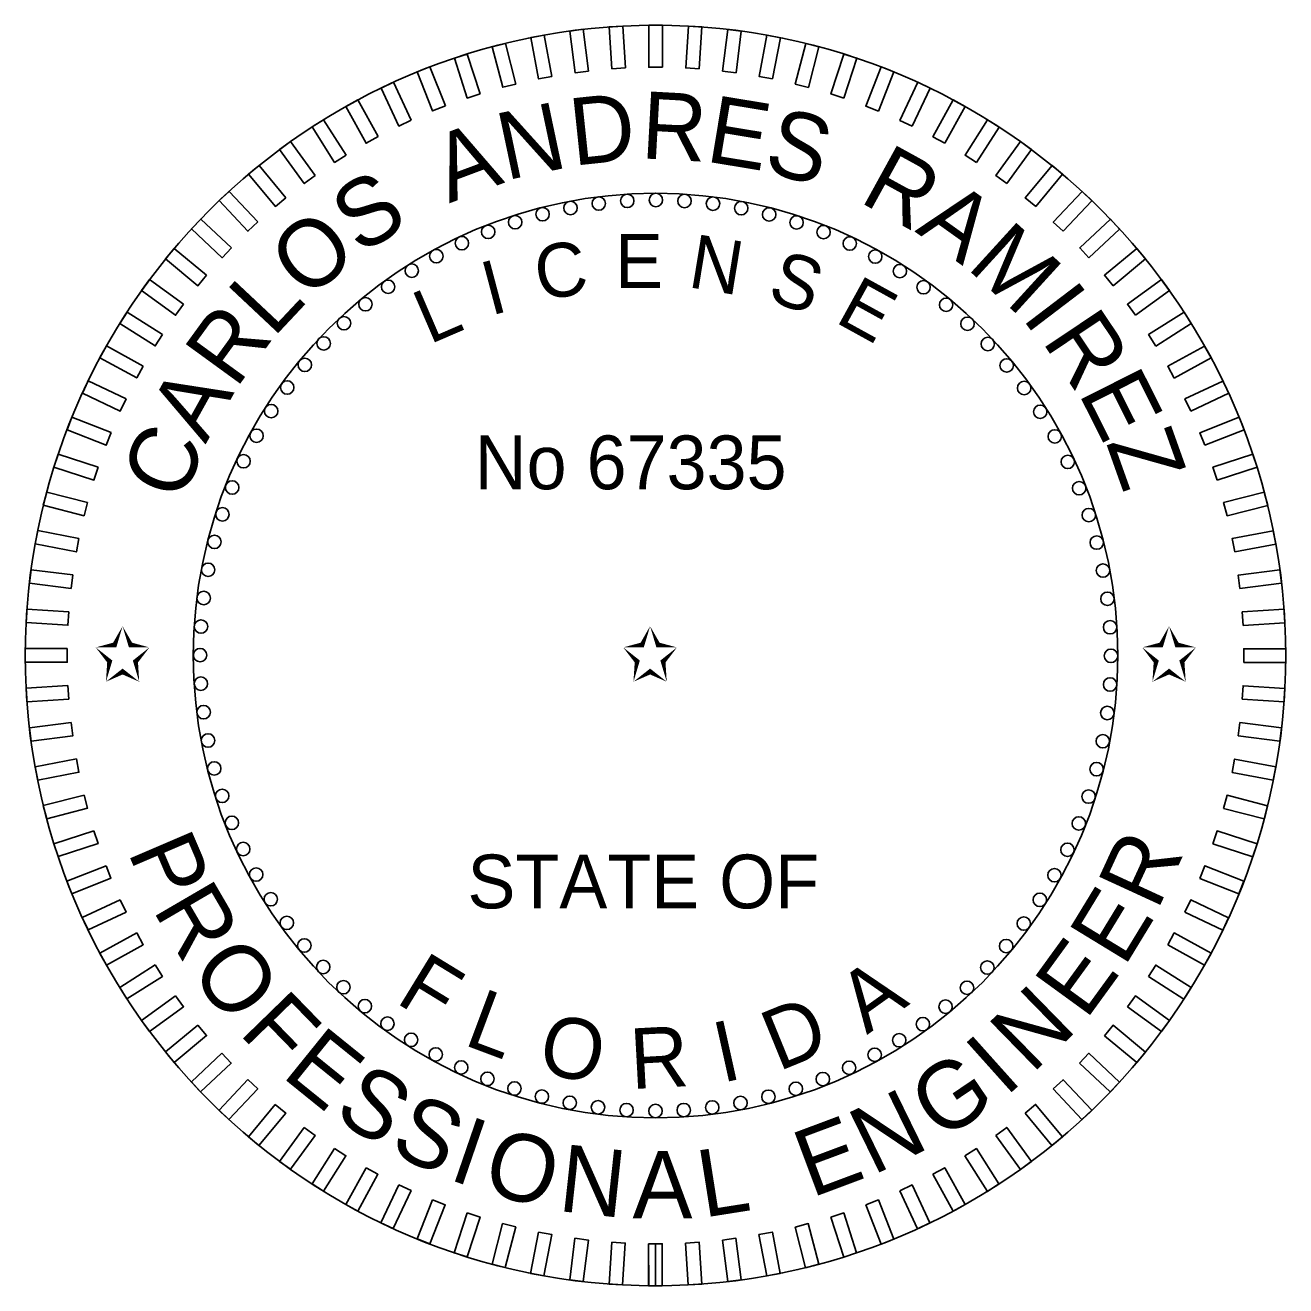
# Model space of a CAD drawing. Extents: x -0.86 to 1.33, y -1.26 to 1.83.
# Drawn here: x 0.0936 to 0.2497, y 1.6752 to 1.8314 of the extents above; entities that cross this region are included whole.
import ezdxf

# ---------------------------------------------------------------- set-up
doc = ezdxf.new("R2010")
doc.units = 0
for name, color, linetype in [('FLMap1', 7, 'Continuous'), ('FLMap3', 7, 'Continuous'), ('TextMisc', 7, 'Continuous')]:
    doc.layers.add(name, color=color, linetype=linetype)

msp = doc.modelspace()

# ---------------------------------------------------------------- linework, layer by layer
at = {"layer": 'FLMap1'}
for radius in [0.07809, 0.05727]:
    msp.add_circle((0.17165, 1.75334), radius, dxfattribs=at)
at = {"layer": 'FLMap3'}
for p, q in [((0.17082, 1.67525), (0.1708, 1.68045)), ((0.17165, 1.67525), (0.17163, 1.68046)), ((0.17248, 1.67525), (0.17247, 1.68046))]:
    msp.add_line(p, q, dxfattribs=at)
for points in [[(0.16336, 1.82576), (0.16169, 1.82555), (0.16104, 1.83071), (0.1627, 1.83093)], [(0.16792, 1.82614), (0.16624, 1.82604), (0.16591, 1.83123), (0.16759, 1.83133)], [(0.1725, 1.82623), (0.17082, 1.82623), (0.17082, 1.83143), (0.1725, 1.83143)], [(0.17707, 1.82604), (0.17539, 1.82614), (0.17572, 1.83133), (0.1774, 1.83123)], [(0.18163, 1.82555), (0.17996, 1.82576), (0.18061, 1.83092), (0.18228, 1.83071)], [(0.15434, 1.82415), (0.15272, 1.82374), (0.15142, 1.82877), (0.15305, 1.82919)], [(0.15882, 1.8251), (0.15717, 1.82479), (0.1562, 1.8299), (0.15785, 1.83021)], [(0.18614, 1.82478), (0.18449, 1.8251), (0.18546, 1.83021), (0.18712, 1.82989)], [(0.1906, 1.82373), (0.18897, 1.82415), (0.19026, 1.82919), (0.19189, 1.82877)], [(0.14993, 1.82293), (0.14833, 1.82241), (0.14673, 1.82736), (0.14832, 1.82787)], [(0.19498, 1.8224), (0.19338, 1.82292), (0.19499, 1.82787), (0.19659, 1.82735)], [(0.14561, 1.82143), (0.14404, 1.82081), (0.14213, 1.82564), (0.14369, 1.82626)], [(0.19927, 1.8208), (0.19771, 1.82142), (0.19962, 1.82626), (0.20119, 1.82564)], [(0.14138, 1.81966), (0.13986, 1.81894), (0.13765, 1.82365), (0.13917, 1.82436)], [(0.20345, 1.81893), (0.20193, 1.81965), (0.20415, 1.82436), (0.20567, 1.82364)], [(0.13728, 1.81763), (0.1358, 1.81682), (0.1333, 1.82137), (0.13477, 1.82218)], [(0.20751, 1.81681), (0.20603, 1.81762), (0.20854, 1.82218), (0.21001, 1.82137)], [(0.13331, 1.81534), (0.13189, 1.81444), (0.1291, 1.81883), (0.13052, 1.81973)], [(0.21142, 1.81443), (0.21, 1.81533), (0.21279, 1.81972), (0.21421, 1.81882)], [(0.12949, 1.81281), (0.12813, 1.81182), (0.12507, 1.81603), (0.12644, 1.81702)], [(0.21518, 1.81181), (0.21382, 1.8128), (0.21688, 1.81701), (0.21824, 1.81602)], [(0.12584, 1.81005), (0.12455, 1.80898), (0.12123, 1.81298), (0.12253, 1.81405)], [(0.21877, 1.80897), (0.21747, 1.81004), (0.22078, 1.81404), (0.22208, 1.81297)], [(0.12237, 1.80706), (0.12115, 1.80591), (0.11759, 1.8097), (0.11881, 1.81085)], [(0.22216, 1.8059), (0.22094, 1.80705), (0.2245, 1.81084), (0.22573, 1.80969)], [(0.1191, 1.80386), (0.11794, 1.80263), (0.11415, 1.80619), (0.1153, 1.80742)], [(0.22536, 1.80262), (0.22421, 1.80385), (0.22801, 1.80741), (0.22916, 1.80618)], [(0.11603, 1.80046), (0.11496, 1.79916), (0.11095, 1.80248), (0.11202, 1.80377)], [(0.22835, 1.79915), (0.22728, 1.80045), (0.23129, 1.80376), (0.23236, 1.80247)], [(0.11318, 1.79687), (0.11219, 1.79551), (0.10798, 1.79857), (0.10897, 1.79993)], [(0.23112, 1.7955), (0.23013, 1.79686), (0.23434, 1.79992), (0.23533, 1.79856)], [(0.11056, 1.79312), (0.10966, 1.7917), (0.10527, 1.79448), (0.10617, 1.7959)], [(0.23365, 1.79168), (0.23275, 1.7931), (0.23714, 1.79589), (0.23804, 1.79447)], [(0.10818, 1.7892), (0.10737, 1.78773), (0.10282, 1.79023), (0.10363, 1.79171)], [(0.23593, 1.78771), (0.23512, 1.78919), (0.23968, 1.79169), (0.24049, 1.79022)], [(0.10606, 1.78515), (0.10534, 1.78362), (0.10064, 1.78584), (0.10135, 1.78736)], [(0.23796, 1.78361), (0.23725, 1.78513), (0.24195, 1.78735), (0.24267, 1.78583)], [(0.10419, 1.78096), (0.10357, 1.7794), (0.09874, 1.78132), (0.09935, 1.78288)], [(0.23973, 1.77939), (0.23911, 1.78095), (0.24395, 1.78287), (0.24457, 1.7813)], [(0.10259, 1.77667), (0.10207, 1.77508), (0.09712, 1.77668), (0.09764, 1.77828)], [(0.24123, 1.77506), (0.24071, 1.77666), (0.24566, 1.77827), (0.24618, 1.77667)], [(0.10126, 1.77229), (0.10084, 1.77066), (0.0958, 1.77196), (0.09622, 1.77359)], [(0.24246, 1.77065), (0.24204, 1.77228), (0.24708, 1.77357), (0.2475, 1.77194)], [(0.10021, 1.76784), (0.09989, 1.76618), (0.09479, 1.76716), (0.0951, 1.76881)], [(0.24341, 1.76617), (0.24309, 1.76782), (0.2482, 1.76879), (0.24852, 1.76714)], [(0.09944, 1.76332), (0.09923, 1.76165), (0.09407, 1.7623), (0.09428, 1.76397)], [(0.24407, 1.76164), (0.24386, 1.76331), (0.24902, 1.76396), (0.24923, 1.76229)], [(0.09896, 1.75877), (0.09885, 1.75709), (0.09366, 1.75742), (0.09377, 1.75909)], [(0.24445, 1.75707), (0.24434, 1.75875), (0.24953, 1.75908), (0.24964, 1.7574)], [(0.09876, 1.75419), (0.09876, 1.75251), (0.09356, 1.75251), (0.09356, 1.75419)], [(0.24454, 1.75249), (0.24454, 1.75418), (0.24974, 1.75418), (0.24974, 1.75249)], [(0.09885, 1.74961), (0.09896, 1.74794), (0.09376, 1.74761), (0.09366, 1.74929)], [(0.24434, 1.74792), (0.24445, 1.7496), (0.24964, 1.74927), (0.24953, 1.74759)], [(0.09923, 1.74505), (0.09944, 1.74338), (0.09428, 1.74273), (0.09407, 1.7444)], [(0.24386, 1.74337), (0.24407, 1.74503), (0.24923, 1.74438), (0.24902, 1.74271)], [(0.09989, 1.74052), (0.10021, 1.73887), (0.0951, 1.73789), (0.09478, 1.73954)], [(0.24309, 1.73885), (0.2434, 1.7405), (0.24851, 1.73953), (0.2482, 1.73788)], [(0.10084, 1.73604), (0.10126, 1.73441), (0.09622, 1.73312), (0.0958, 1.73474)], [(0.24204, 1.73439), (0.24246, 1.73602), (0.24749, 1.73473), (0.24708, 1.7331)], [(0.10206, 1.73163), (0.10258, 1.73003), (0.09764, 1.72842), (0.09712, 1.73002)], [(0.24071, 1.73001), (0.24123, 1.73161), (0.24618, 1.73), (0.24566, 1.7284)], [(0.10357, 1.7273), (0.10418, 1.72574), (0.09935, 1.72382), (0.09873, 1.72538)], [(0.23911, 1.72572), (0.23973, 1.72729), (0.24456, 1.72537), (0.24394, 1.72381)], [(0.10534, 1.72308), (0.10605, 1.72155), (0.10135, 1.71934), (0.10063, 1.72086)], [(0.23724, 1.72154), (0.23796, 1.72306), (0.24266, 1.72085), (0.24195, 1.71933)], [(0.10737, 1.71897), (0.10818, 1.7175), (0.10362, 1.71499), (0.10281, 1.71647)], [(0.23511, 1.71748), (0.23592, 1.71896), (0.24048, 1.71645), (0.23967, 1.71498)], [(0.10965, 1.715), (0.11055, 1.71358), (0.10616, 1.7108), (0.10526, 1.71222)], [(0.23274, 1.71357), (0.23364, 1.71499), (0.23803, 1.7122), (0.23713, 1.71078)], [(0.11218, 1.71119), (0.11317, 1.70983), (0.10896, 1.70677), (0.10797, 1.70813)], [(0.23012, 1.70981), (0.23111, 1.71117), (0.23532, 1.70812), (0.23433, 1.70676)], [(0.11495, 1.70754), (0.11602, 1.70624), (0.11201, 1.70292), (0.11094, 1.70422)], [(0.22727, 1.70623), (0.22834, 1.70752), (0.23235, 1.70421), (0.23128, 1.70291)], [(0.11793, 1.70407), (0.11909, 1.70284), (0.11529, 1.69928), (0.11414, 1.7005)], [(0.2242, 1.70283), (0.22535, 1.70405), (0.22915, 1.70049), (0.22799, 1.69927)], [(0.12113, 1.70079), (0.12236, 1.69964), (0.1188, 1.69585), (0.11757, 1.697)], [(0.22093, 1.69963), (0.22215, 1.70078), (0.22571, 1.69699), (0.22449, 1.69584)], [(0.12453, 1.69772), (0.12583, 1.69665), (0.12251, 1.69264), (0.12122, 1.69371)], [(0.21746, 1.69664), (0.21875, 1.69771), (0.22207, 1.6937), (0.22077, 1.69263)], [(0.12812, 1.69487), (0.12948, 1.69388), (0.12642, 1.68968), (0.12506, 1.69066)], [(0.21381, 1.69388), (0.21517, 1.69486), (0.21822, 1.69066), (0.21686, 1.68967)], [(0.13188, 1.69225), (0.1333, 1.69135), (0.13051, 1.68696), (0.12909, 1.68786)], [(0.20999, 1.69135), (0.21141, 1.69225), (0.2142, 1.68786), (0.21278, 1.68695)], [(0.13579, 1.68988), (0.13726, 1.68907), (0.13476, 1.68451), (0.13329, 1.68532)], [(0.20602, 1.68906), (0.20749, 1.68987), (0.21, 1.68531), (0.20853, 1.6845)], [(0.13985, 1.68775), (0.14137, 1.68704), (0.13915, 1.68233), (0.13763, 1.68305)], [(0.20192, 1.68703), (0.20344, 1.68775), (0.20565, 1.68304), (0.20413, 1.68232)], [(0.14403, 1.68588), (0.14559, 1.68527), (0.14368, 1.68043), (0.14211, 1.68105)], [(0.19769, 1.68526), (0.19926, 1.68588), (0.20117, 1.68104), (0.19961, 1.68042)], [(0.14832, 1.68428), (0.14992, 1.68376), (0.14831, 1.67882), (0.14671, 1.67934)], [(0.19337, 1.68376), (0.19497, 1.68428), (0.19657, 1.67933), (0.19497, 1.67881)], [(0.1527, 1.68295), (0.15433, 1.68254), (0.15304, 1.6775), (0.15141, 1.67792)], [(0.18895, 1.68253), (0.19058, 1.68295), (0.19188, 1.67791), (0.19025, 1.67749)], [(0.15716, 1.6819), (0.15881, 1.68159), (0.15783, 1.67648), (0.15618, 1.67679)], [(0.16167, 1.68113), (0.16334, 1.68092), (0.16269, 1.67576), (0.16102, 1.67597)], [(0.16623, 1.68065), (0.1679, 1.68054), (0.16758, 1.67535), (0.1659, 1.67546)], [(0.17538, 1.68054), (0.17706, 1.68065), (0.17738, 1.67546), (0.17571, 1.67535)], [(0.17994, 1.68092), (0.18161, 1.68113), (0.18226, 1.67597), (0.1806, 1.67576)], [(0.18447, 1.68159), (0.18613, 1.6819), (0.1871, 1.67679), (0.18545, 1.67648)], [(0.1708, 1.68045), (0.17248, 1.68045), (0.17248, 1.67525), (0.1708, 1.67525)]]:
    msp.add_lwpolyline(points, close=True, dxfattribs=at)
for centre in [(0.16815, 1.80967), (0.1717, 1.80978), (0.17524, 1.80966), (0.15766, 1.80802), (0.16112, 1.80879), (0.16462, 1.80934), (0.17877, 1.80933), (0.18227, 1.80877), (0.18573, 1.80799), (0.15426, 1.80703), (0.18913, 1.807), (0.15092, 1.80583), (0.19247, 1.8058), (0.14766, 1.80443), (0.19572, 1.80439), (0.1445, 1.80282), (0.19888, 1.80277), (0.14145, 1.80102), (0.20193, 1.80097), (0.13852, 1.79903), (0.20486, 1.79897), (0.13571, 1.79686), (0.20766, 1.7968), (0.13305, 1.79451), (0.21031, 1.79445), (0.13054, 1.79201), (0.21282, 1.79194), (0.1282, 1.78935), (0.21516, 1.78928), (0.12602, 1.78655), (0.21733, 1.78648), (0.12403, 1.78362), (0.21932, 1.78354), (0.12222, 1.78057), (0.22112, 1.78049), (0.12061, 1.77741), (0.22273, 1.77733), (0.1192, 1.77416), (0.22414, 1.77407), (0.11799, 1.77083), (0.22534, 1.77074), (0.117, 1.76742), (0.22632, 1.76733), (0.11622, 1.76396), (0.22709, 1.76387), (0.11567, 1.76046), (0.22764, 1.76037), (0.11533, 1.75693), (0.22797, 1.75684), (0.11522, 1.75339), (0.22808, 1.7533), (0.11532, 1.74985), (0.22797, 1.74975), (0.11566, 1.74632), (0.22763, 1.74622), (0.11621, 1.74281), (0.22707, 1.74272), (0.11698, 1.73935), (0.2263, 1.73926), (0.11796, 1.73595), (0.22531, 1.73586), (0.11916, 1.73261), (0.2241, 1.73253), (0.12057, 1.72936), (0.22269, 1.72927), (0.12217, 1.7262), (0.22108, 1.72612), (0.12398, 1.72314), (0.21927, 1.72307), (0.12597, 1.72021), (0.21728, 1.72013), (0.12814, 1.71741), (0.2151, 1.71734), (0.13048, 1.71475), (0.21276, 1.71468), (0.13298, 1.71224), (0.21025, 1.71217), (0.13564, 1.70989), (0.20759, 1.70983), (0.13844, 1.70772), (0.20478, 1.70766), (0.14137, 1.70572), (0.20185, 1.70567), (0.14442, 1.70391), (0.1988, 1.70387), (0.14758, 1.7023), (0.19564, 1.70226), (0.15083, 1.70089), (0.19238, 1.70086), (0.15417, 1.69969), (0.15757, 1.69869), (0.18564, 1.69867), (0.18904, 1.69966), (0.16103, 1.69792), (0.16453, 1.69736), (0.16806, 1.69702), (0.17515, 1.69702), (0.17868, 1.69735), (0.18218, 1.6979), (0.17165, 1.69691)]:
    msp.add_circle(centre, 0.000833, dxfattribs=at)

# ---------------------------------------------------------------- texts
for s, rotation, p in [('C', 8.9826, (0.15724, 1.79731)), ('E', 359.9662, (0.16663, 1.79889)), ('N', 350.6464, (0.17553, 1.79901)), ('S', 341.04, (0.18529, 1.79744)), ('I', 14.8189, (0.1512, 1.79543)), ('E', 331.1686, (0.19374, 1.79473)), ('L', 23.3052, (0.14365, 1.79186))]:
    msp.add_text(s, height=0.00666, rotation=rotation, dxfattribs=at).set_placement(p)
for p in [(0.1021, 1.75018), (0.16746, 1.75018), (0.23176, 1.75018)]:
    msp.add_text('✩', height=0.00666, dxfattribs=at).set_placement(p)
at = {"layer": 'TextMisc'}
for s, height, rotation, p in [('D', 0.00833, 6.0117, (0.16146, 1.81402)), ('R', 0.00833, 356.8926, (0.16975, 1.81495)), ('N', 0.00833, 11.9184, (0.15311, 1.8122)), ('E', 0.00833, 350.6464, (0.17771, 1.81458)), ('S', 0.00833, 344.2727, (0.1848, 1.81344)), ('A', 0.00833, 20.5125, (0.1461, 1.80936)), ('R', 0.00833, 331.1686, (0.19673, 1.80964)), ('S', 0.00833, 31.466, (0.13501, 1.80293)), ('A', 0.00833, 324.4537, (0.2037, 1.80591)), ('O', 0.00833, 39.3, (0.12836, 1.79728)), ('M', 0.00833, 317.6422, (0.21007, 1.80141)), ('L', 0.00833, 46.8094, (0.12427, 1.79262)), ('I', 0.00833, 307.2662, (0.21692, 1.79526)), ('R', 0.00833, 53.9986, (0.11966, 1.78628)), ('R', 0.00833, 303.7708, (0.21944, 1.79235)), ('E', 0.00833, 296.7339, (0.22399, 1.78593)), ('A', 0.00833, 60.8746, (0.11589, 1.77946)), ('C', 0.00833, 67.4457, (0.11294, 1.77214)), ('Z', 0.00833, 289.646, (0.22744, 1.77972)), ('P', 0.00833, 293.1955, (0.1062, 1.72906)), ('R', 0.00833, 65.2886, (0.23382, 1.72161)), ('R', 0.00833, 300.2595, (0.10927, 1.7219)), ('E', 0.00833, 58.6169, (0.22972, 1.71462)), ('E', 0.00833, 53.9986, (0.22496, 1.70806)), ('O', 0.00833, 307.2662, (0.11378, 1.71425)), ('F', 0.0075, 328.534, (0.13929, 1.71042)), ('A', 0.0075, 35.5463, (0.19784, 1.70631)), ('L', 0.0075, 339.4875, (0.14772, 1.70517)), ('N', 0.00833, 44.3421, (0.21829, 1.70141)), ('F', 0.00833, 314.2033, (0.1199, 1.70655)), ('D', 0.0075, 22.2223, (0.18687, 1.70177)), ('O', 0.0075, 348.0816, (0.15684, 1.70179)), ('E', 0.00833, 321.0594, (0.12518, 1.70125)), ('R', 0.0075, 3.1074, (0.16868, 1.69961)), ('I', 0.0075, 12.5248, (0.17986, 1.70037)), ('I', 0.00833, 41.8391, (0.21501, 1.69855)), ('G', 0.00833, 34.1136, (0.207, 1.69306)), ('S', 0.00833, 327.8239, (0.13153, 1.69621)), ('N', 0.00833, 26.0618, (0.19857, 1.68888)), ('S', 0.00833, 334.487, (0.13845, 1.69193)), ('E', 0.00833, 20.5125, (0.19095, 1.68611)), ('I', 0.00833, 341.04, (0.14583, 1.68849)), ('O', 0.00833, 344.2727, (0.14992, 1.68702)), ('N', 0.00833, 353.7858, (0.15945, 1.68453)), ('A', 0.00833, 359.9662, (0.1688, 1.68361)), ('L', 0.00833, 8.9826, (0.1776, 1.68368))]:
    msp.add_text(s, height=height, rotation=rotation, dxfattribs=at).set_placement(p)
for s, p in [('No 67335', (0.14924, 1.77394)), ('STATE OF', (0.14835, 1.72201))]:
    msp.add_text(s, height=0.006664, dxfattribs=at).set_placement(p)

doc.saveas('drawing.dxf')
